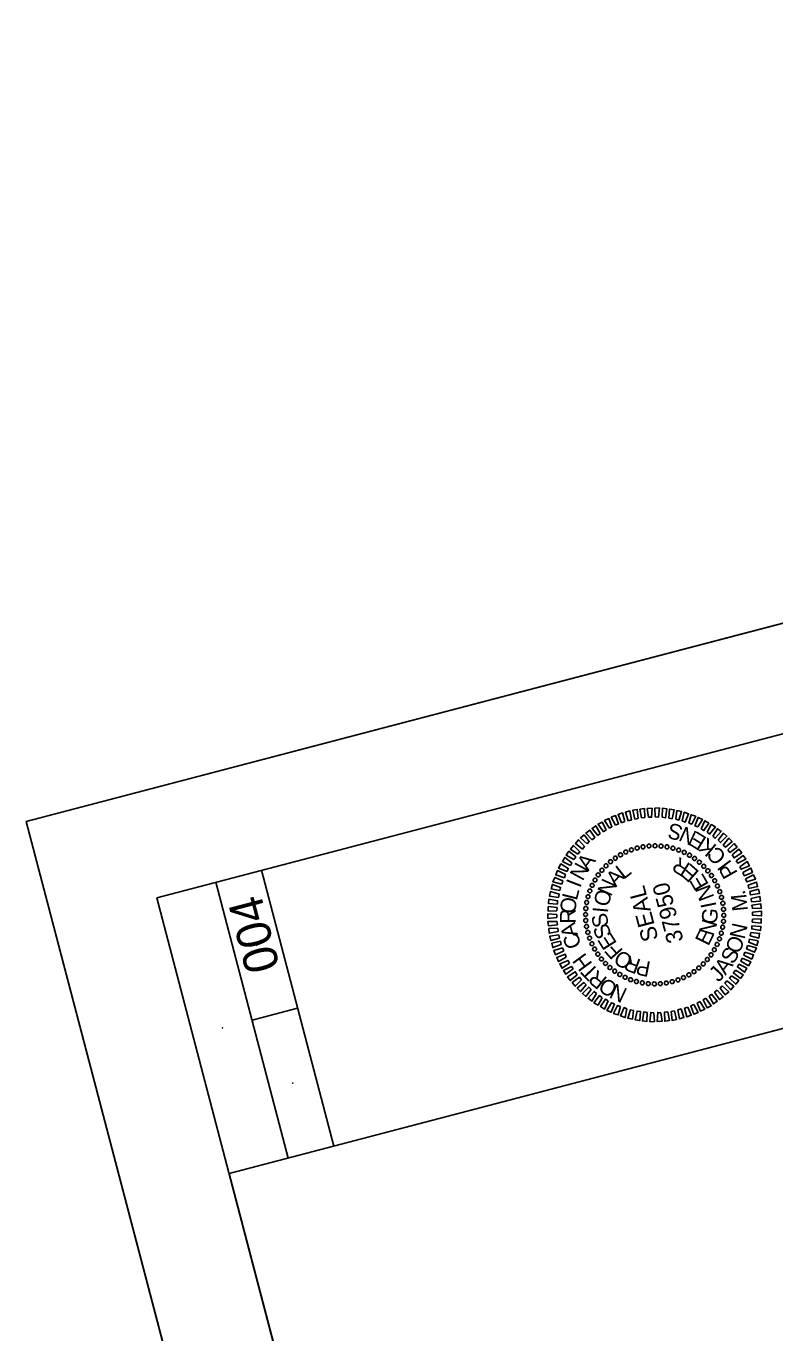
# Model space of a CAD drawing. Extents: x 1366711 to 1368206, y 878140 to 880064.
# Drawn here: x 1366710.8 to 1366973.2, y 879605.6 to 880063.8 of the extents above; entities that cross this region are included whole.
import ezdxf

# ---------------------------------------------------------------- set-up
doc = ezdxf.new("R2010")
doc.units = 0
for name, color, linetype in [('Exist Hydro Jurisdictional Stream or Body of Water Mitigable Cogo Number', 7, 'Continuous'), ('Exist Hydro Jurisdictional Stream or Body of Water NonMitigable', 7, 'Continuous'), ('Exist Hydro Jurisdictional Stream or Body of Water NonMitigable Text', 7, 'Continuous'), ('Sheet_Data_Field_CELL', 7, 'Continuous'), ('Sheet_Data_Text_CELL', 7, 'Continuous'), ('Sheet_Plan_CELL', 7, 'Continuous')]:
    doc.layers.add(name, color=color, linetype=linetype)

msp = doc.modelspace()

# ---------------------------------------------------------------- linework, layer by layer
at = {"layer": 'Exist Hydro Jurisdictional Stream or Body of Water Mitigable Cogo Number'}
for p, q in [((1367748.14, 880017.97), (1366756.62, 879758.15)), ((1367773.49, 879921.24), (1366781.97, 879661.42)), ((1366777.34, 879763.58), (1366802.69, 879666.85)), ((1366793.3, 879767.77), (1366818.65, 879671.03)), ((1366756.62, 879758.15), (1367168.57, 878186.24)), ((1366805.98, 879719.4), (1366790.02, 879715.22))]:
    msp.add_line(p, q, dxfattribs=at)
at = {"layer": 'Exist Hydro Jurisdictional Stream or Body of Water NonMitigable'}
for p in [(1367774.9, 880063.78), (1367141.8, 878140.46)]:
    msp.add_line(p, (1366710.84, 879784.92), dxfattribs=at)
for centre in [(1366791.66, 879741.49), (1366779.66, 879712.5), (1366804.33, 879693.13)]:
    msp.add_circle(centre, 0.06, dxfattribs=at)
at = {"layer": 'Sheet_Data_Field_CELL'}
for p, q in [((1366919.05, 879773.19), (1366919.05, 879773.19)), ((1366920.99, 879774.13), (1366920.99, 879774.13)), ((1366922.91, 879774.97), (1366922.91, 879774.97)), ((1366924.95, 879775.59), (1366924.95, 879775.59)), ((1366927.03, 879776.03), (1366927.03, 879776.03)), ((1366929.12, 879776.27), (1366929.12, 879776.27)), ((1366931.19, 879776.39), (1366931.19, 879776.39)), ((1366933.33, 879776.29), (1366933.33, 879776.29)), ((1366935.42, 879775.98), (1366935.42, 879775.98)), ((1366937.5, 879775.56), (1366937.5, 879775.56)), ((1366939.5, 879774.86), (1366939.5, 879774.86)), ((1366941.48, 879774.07), (1366941.48, 879774.07)), ((1366943.31, 879773.08), (1366943.31, 879773.08)), ((1366914.06, 879769.38), (1366914.06, 879769.38)), ((1366915.61, 879770.81), (1366915.61, 879770.81)), ((1366917.26, 879772.08), (1366917.26, 879772.08)), ((1366945.14, 879771.93), (1366945.14, 879771.93)), ((1366946.75, 879770.63), (1366946.75, 879770.63)), ((1366948.32, 879769.17), (1366948.32, 879769.17)), ((1366910.14, 879764.37), (1366910.14, 879764.37)), ((1366911.29, 879766.19), (1366911.29, 879766.19)), ((1366912.59, 879767.81), (1366912.59, 879767.81)), ((1366949.76, 879767.61), (1366949.76, 879767.61)), ((1366951.03, 879765.97), (1366951.03, 879765.97)), ((1366952.13, 879764.17), (1366952.13, 879764.17)), ((1366908.36, 879760.55), (1366908.36, 879760.55)), ((1366909.16, 879762.53), (1366909.16, 879762.53)), ((1366953.08, 879762.23), (1366953.08, 879762.23)), ((1366953.92, 879760.31), (1366953.92, 879760.31)), ((1366906.93, 879754.39), (1366906.93, 879754.39)), ((1366907.24, 879756.48), (1366907.24, 879756.48)), ((1366907.67, 879758.55), (1366907.67, 879758.55)), ((1366954.54, 879758.28), (1366954.54, 879758.28)), ((1366954.97, 879756.19), (1366954.97, 879756.19)), ((1366906.83, 879752.25), (1366906.83, 879752.25)), ((1366906.96, 879750.18), (1366906.96, 879750.18)), ((1366931.08, 879752.14), (1366931.08, 879752.14)), ((1366955.21, 879754.1), (1366955.21, 879754.1)), ((1366955.24, 879749.89), (1366955.24, 879749.89)), ((1366955.34, 879752.03), (1366955.34, 879752.03)), ((1366907.19, 879748.09), (1366907.19, 879748.09)), ((1366907.63, 879746), (1366907.63, 879746)), ((1366954.5, 879745.73), (1366954.5, 879745.73)), ((1366954.92, 879747.8), (1366954.92, 879747.8)), ((1366908.25, 879743.97), (1366908.25, 879743.97)), ((1366909.09, 879742.05), (1366909.09, 879742.05)), ((1366953.01, 879741.75), (1366953.01, 879741.75)), ((1366953.81, 879743.73), (1366953.81, 879743.73)), ((1366910.03, 879740.11), (1366910.03, 879740.11)), ((1366911.14, 879738.31), (1366911.14, 879738.31)), ((1366912.41, 879736.66), (1366912.41, 879736.66)), ((1366949.58, 879736.47), (1366949.58, 879736.47)), ((1366950.88, 879738.09), (1366950.88, 879738.09)), ((1366952.02, 879739.91), (1366952.02, 879739.91)), ((1366913.85, 879735.11), (1366913.85, 879735.11)), ((1366915.41, 879733.64), (1366915.41, 879733.64)), ((1366917.03, 879732.34), (1366917.03, 879732.34)), ((1366944.91, 879732.2), (1366944.91, 879732.2)), ((1366946.56, 879733.46), (1366946.56, 879733.46)), ((1366948.11, 879734.9), (1366948.11, 879734.9)), ((1366918.86, 879731.2), (1366918.86, 879731.2)), ((1366920.69, 879730.21), (1366920.69, 879730.21)), ((1366922.67, 879729.41), (1366922.67, 879729.41)), ((1366924.67, 879728.72), (1366924.67, 879728.72)), ((1366926.74, 879728.3), (1366926.74, 879728.3)), ((1366928.84, 879727.99), (1366928.84, 879727.99)), ((1366930.97, 879727.88), (1366930.97, 879727.88)), ((1366933.04, 879728.01), (1366933.04, 879728.01)), ((1366935.13, 879728.25), (1366935.13, 879728.25)), ((1366937.22, 879728.69), (1366937.22, 879728.69)), ((1366939.25, 879729.31), (1366939.25, 879729.31)), ((1366941.17, 879730.14), (1366941.17, 879730.14)), ((1366943.11, 879731.09), (1366943.11, 879731.09))]:
    msp.add_line(p, q, dxfattribs=at)
for points in [[(1366917.35, 879783.54), (1366915.85, 879786.38), (1366917.39, 879786.97), (1366918.41, 879784.04)], [(1366919.5, 879784.45), (1366918.28, 879787.37), (1366919.84, 879787.9), (1366920.59, 879784.86)], [(1366921.81, 879785.14), (1366920.83, 879788.13), (1366922.41, 879788.57), (1366922.93, 879785.46)], [(1366924.15, 879785.75), (1366923.4, 879788.8), (1366924.96, 879789.14), (1366925.29, 879785.97)], [(1366926.45, 879786.15), (1366925.89, 879789.2), (1366927.52, 879789.46), (1366927.63, 879786.23)], [(1366928.93, 879786.44), (1366928.49, 879789.43), (1366930.16, 879789.55), (1366930.01, 879786.34)], [(1366931.32, 879786.46), (1366931.12, 879789.51), (1366932.74, 879789.62), (1366932.4, 879786.37)], [(1366933.75, 879786.39), (1366933.78, 879789.51), (1366935.39, 879789.31), (1366934.87, 879786.15)], [(1366936.06, 879786.04), (1366936.32, 879789.22), (1366937.95, 879788.93), (1366937.21, 879785.86)], [(1366938.46, 879785.71), (1366938.88, 879788.68), (1366940.52, 879788.39), (1366939.5, 879785.4)], [(1366940.77, 879785.15), (1366941.43, 879788.15), (1366943, 879787.58), (1366941.82, 879784.65)], [(1366943.02, 879784.28), (1366943.9, 879787.23), (1366945.49, 879786.73), (1366944.08, 879783.92)], [(1366909.19, 879778.49), (1366907.02, 879780.84), (1366908.34, 879781.87), (1366910.08, 879779.24)], [(1366911.14, 879779.94), (1366909.13, 879782.44), (1366910.43, 879783.36), (1366911.98, 879780.68)], [(1366913.16, 879781.31), (1366911.25, 879783.99), (1366912.71, 879784.7), (1366914.05, 879781.91)], [(1366915.23, 879782.5), (1366913.53, 879785.18), (1366915.03, 879785.9), (1366916.13, 879783.05)], [(1366945.18, 879783.38), (1366946.31, 879786.31), (1366947.81, 879785.63), (1366946.2, 879782.97)], [(1366947.4, 879782.25), (1366948.65, 879785.16), (1366950.04, 879784.29), (1366948.36, 879781.72)], [(1366949.46, 879781.18), (1366950.93, 879783.79), (1366952.36, 879782.99), (1366950.36, 879780.47)], [(1366951.43, 879779.72), (1366953.1, 879782.34), (1366954.42, 879781.36), (1366952.28, 879779.01)], [(1366905.74, 879775.22), (1366903.29, 879777.19), (1366904.43, 879778.46), (1366906.49, 879776.13)], [(1366907.45, 879777), (1366905.09, 879779.15), (1366906.36, 879780.16), (1366908.18, 879777.81)], [(1366953.32, 879778.34), (1366955.2, 879780.73), (1366956.43, 879779.77), (1366954.16, 879777.48)], [(1366955.05, 879776.62), (1366957.08, 879779.05), (1366958.23, 879777.82), (1366955.86, 879775.9)], [(1366902.76, 879771.57), (1366900.06, 879773.12), (1366901.04, 879774.45), (1366903.5, 879772.48)], [(1366904.18, 879773.47), (1366901.59, 879775.2), (1366902.69, 879776.47), (1366904.9, 879774.28)], [(1366956.73, 879774.94), (1366958.92, 879777.16), (1366959.97, 879775.9), (1366957.44, 879774.03)], [(1366958.28, 879773.17), (1366960.64, 879775.14), (1366961.59, 879773.9), (1366958.89, 879772.08)], [(1366959.66, 879771.1), (1366962.15, 879772.95), (1366962.98, 879771.63), (1366960.26, 879770.21)], [(1366900.38, 879767.34), (1366897.43, 879768.57), (1366898.23, 879770), (1366900.83, 879768.42)], [(1366901.54, 879769.47), (1366898.79, 879770.86), (1366899.6, 879772.29), (1366902.09, 879770.38)], [(1366960.89, 879769.04), (1366963.55, 879770.84), (1366964.32, 879769.34), (1366961.4, 879768.13)], [(1366962.03, 879766.95), (1366964.8, 879768.53), (1366965.37, 879767.03), (1366962.49, 879765.87)], [(1366898.58, 879762.87), (1366895.42, 879763.74), (1366896.06, 879765.23), (1366898.85, 879764.05)], [(1366899.44, 879765.17), (1366896.4, 879766.17), (1366897.08, 879767.67), (1366899.84, 879766.24)], [(1366962.94, 879764.79), (1366965.77, 879766.14), (1366966.4, 879764.62), (1366963.39, 879763.72)], [(1366963.82, 879762.54), (1366966.78, 879763.62), (1366967.16, 879762.07), (1366964.09, 879761.41)], [(1366897.36, 879758.27), (1366894.29, 879758.66), (1366894.54, 879760.28), (1366897.59, 879759.44)], [(1366897.83, 879760.71), (1366894.83, 879761.22), (1366895.23, 879762.83), (1366898.14, 879761.75)], [(1366964.41, 879760.29), (1366967.43, 879761.14), (1366967.81, 879759.59), (1366964.67, 879759.16)], [(1366896.82, 879753.6), (1366893.74, 879753.49), (1366893.8, 879755.06), (1366896.87, 879754.67)], [(1366897.07, 879755.93), (1366893.84, 879756.18), (1366894.03, 879757.64), (1366897.09, 879757.09)], [(1366964.92, 879757.93), (1366967.99, 879758.59), (1366968.14, 879756.98), (1366965.04, 879756.76)], [(1366965.17, 879755.59), (1366968.26, 879756.01), (1366968.46, 879754.41), (1366965.35, 879754.44)], [(1366896.84, 879751.2), (1366893.69, 879750.82), (1366893.62, 879752.5), (1366896.8, 879752.24)], [(1366896.99, 879748.69), (1366893.9, 879748.27), (1366893.7, 879749.87), (1366896.82, 879749.84)], [(1366965.35, 879750.68), (1366968.43, 879750.79), (1366968.37, 879749.22), (1366965.3, 879749.61)], [(1366965.33, 879753.08), (1366968.48, 879753.46), (1366968.55, 879751.78), (1366965.37, 879752.04)], [(1366897.25, 879746.35), (1366894.17, 879745.69), (1366894.02, 879747.3), (1366897.12, 879747.52)], [(1366964.8, 879746.01), (1366967.87, 879745.62), (1366967.63, 879743.99), (1366964.58, 879744.84)], [(1366965.1, 879748.35), (1366968.33, 879748.1), (1366968.14, 879746.65), (1366965.08, 879747.19)], [(1366897.76, 879743.99), (1366894.74, 879743.14), (1366894.36, 879744.68), (1366897.5, 879745.12)], [(1366898.34, 879741.74), (1366895.39, 879740.66), (1366895, 879742.21), (1366898.08, 879742.87)], [(1366963.59, 879741.41), (1366966.74, 879740.53), (1366966.1, 879739.05), (1366963.32, 879740.23)], [(1366964.33, 879743.57), (1366967.34, 879743.06), (1366966.94, 879741.45), (1366964.03, 879742.53)], [(1366899.23, 879739.48), (1366896.39, 879738.13), (1366895.77, 879739.66), (1366898.77, 879740.56)], [(1366900.13, 879737.33), (1366897.37, 879735.75), (1366896.8, 879737.24), (1366899.68, 879738.41)], [(1366901.27, 879735.24), (1366898.62, 879733.44), (1366897.85, 879734.93), (1366900.76, 879736.15)], [(1366961.79, 879736.93), (1366964.74, 879735.71), (1366963.93, 879734.28), (1366961.33, 879735.86)], [(1366962.73, 879739.11), (1366965.77, 879738.11), (1366965.09, 879736.61), (1366962.33, 879738.04)], [(1366902.5, 879733.18), (1366900.01, 879731.33), (1366899.19, 879732.65), (1366901.9, 879734.06)], [(1366903.89, 879731.11), (1366901.53, 879729.14), (1366900.58, 879730.38), (1366903.28, 879732.19)], [(1366959.41, 879732.71), (1366962.1, 879731.16), (1366961.12, 879729.83), (1366958.66, 879731.8)], [(1366960.63, 879734.8), (1366963.37, 879733.42), (1366962.57, 879731.99), (1366960.08, 879733.9)], [(1366905.44, 879729.34), (1366903.25, 879727.12), (1366902.2, 879728.38), (1366904.73, 879730.24)], [(1366907.11, 879727.65), (1366905.09, 879725.23), (1366903.94, 879726.46), (1366906.31, 879728.38)], [(1366954.72, 879727.28), (1366957.07, 879725.13), (1366955.8, 879724.13), (1366953.99, 879726.47)], [(1366956.42, 879729.06), (1366958.88, 879727.09), (1366957.74, 879725.82), (1366955.68, 879728.15)], [(1366957.99, 879730.81), (1366960.58, 879729.07), (1366959.48, 879727.81), (1366957.26, 879730)], [(1366908.85, 879725.93), (1366906.96, 879723.55), (1366905.74, 879724.51), (1366908.01, 879726.8)], [(1366910.74, 879724.56), (1366909.07, 879721.93), (1366907.74, 879722.92), (1366909.89, 879725.27)], [(1366912.7, 879723.1), (1366911.23, 879720.48), (1366909.8, 879721.29), (1366911.81, 879723.81)], [(1366914.76, 879722.03), (1366913.52, 879719.12), (1366912.13, 879719.98), (1366913.81, 879722.56)], [(1366949.01, 879722.97), (1366950.91, 879720.29), (1366949.45, 879719.58), (1366948.12, 879722.37)], [(1366951.03, 879724.34), (1366953.03, 879721.84), (1366951.74, 879720.93), (1366950.18, 879723.6)], [(1366952.98, 879725.79), (1366955.14, 879723.44), (1366953.82, 879722.41), (1366952.09, 879725.03)], [(1366916.98, 879720.9), (1366915.85, 879717.97), (1366914.36, 879718.65), (1366915.97, 879721.31)], [(1366919.14, 879720), (1366918.27, 879717.04), (1366916.67, 879717.55), (1366918.09, 879720.36)], [(1366921.39, 879719.13), (1366920.73, 879716.13), (1366919.17, 879716.69), (1366920.35, 879719.63)], [(1366923.71, 879718.57), (1366923.29, 879715.59), (1366921.65, 879715.89), (1366922.67, 879718.88)], [(1366926.11, 879718.24), (1366925.85, 879715.06), (1366924.21, 879715.35), (1366924.95, 879718.42)], [(1366928.41, 879717.89), (1366928.39, 879714.77), (1366926.77, 879714.97), (1366927.29, 879718.12)], [(1366930.84, 879717.81), (1366931.05, 879714.76), (1366929.42, 879714.66), (1366929.76, 879717.91)], [(1366933.24, 879717.84), (1366933.68, 879714.85), (1366932.01, 879714.73), (1366932.16, 879717.94)], [(1366935.72, 879718.13), (1366936.27, 879715.08), (1366934.64, 879714.82), (1366934.54, 879718.05)], [(1366938.01, 879718.53), (1366938.77, 879715.48), (1366937.21, 879715.14), (1366936.87, 879718.3)], [(1366940.35, 879719.13), (1366941.34, 879716.15), (1366939.76, 879715.71), (1366939.24, 879718.82)], [(1366942.66, 879719.83), (1366943.88, 879716.91), (1366942.33, 879716.38), (1366941.57, 879719.42)], [(1366944.82, 879720.74), (1366946.31, 879717.9), (1366944.78, 879717.31), (1366943.75, 879720.24)], [(1366946.93, 879721.78), (1366948.64, 879719.1), (1366947.13, 879718.38), (1366946.03, 879721.23)]]:
    msp.add_lwpolyline(points, close=True, dxfattribs=at)
for centre, major_axis, ratio in [((1366917.3, 879772.05), (-0.394, 0.573), 0.999706), ((1366919.09, 879773.18), (-0.343, 0.605), 0.999706), ((1366920.97, 879774.14), (-0.289, 0.632), 0.999706), ((1366922.92, 879774.94), (-0.234, 0.655), 0.999706), ((1366924.94, 879775.57), (-0.176, 0.673), 0.999706), ((1366927.01, 879776.01), (-0.117, 0.685), 0.999706), ((1366929.1, 879776.28), (-0.058, 0.693), 0.999706), ((1366931.22, 879776.36), (0.002, 0.695), 0.999706), ((1366933.33, 879776.25), (0.063, 0.693), 0.999706), ((1366935.42, 879775.97), (0.122, 0.684), 0.999707), ((1366937.48, 879775.5), (0.181, 0.671), 0.999707), ((1366939.49, 879774.85), (0.239, 0.653), 0.999707), ((1366941.44, 879774.03), (0.295, 0.63), 0.999708), ((1366943.31, 879773.05), (0.348, 0.602), 0.999708), ((1366945.08, 879771.9), (0.4, 0.569), 0.999709), ((1366912.61, 879767.81), (-0.528, 0.452), 0.999707), ((1366914.05, 879769.36), (-0.487, 0.496), 0.999707), ((1366915.62, 879770.78), (-0.442, 0.537), 0.999707), ((1366946.75, 879770.61), (0.448, 0.532), 0.999709), ((1366948.3, 879769.17), (0.493, 0.491), 0.99971), ((1366949.72, 879767.6), (0.534, 0.446), 0.99971), ((1366910.17, 879764.36), (-0.599, 0.353), 0.999708), ((1366911.32, 879766.14), (-0.566, 0.404), 0.999708), ((1366951, 879765.92), (0.571, 0.397), 0.99971), ((1366952.13, 879764.13), (0.603, 0.346), 0.99971), ((1366907.72, 879758.53), (-0.67, 0.186), 0.99971), ((1366908.37, 879760.55), (-0.651, 0.244), 0.999709), ((1366909.19, 879762.49), (-0.627, 0.3), 0.999709), ((1366953.09, 879762.25), (0.631, 0.291), 0.999711), ((1366953.89, 879760.3), (0.655, 0.235), 0.999711), ((1366954.51, 879758.28), (0.673, 0.176), 0.999711), ((1366906.97, 879754.38), (-0.692, 0.066), 0.99971), ((1366907.25, 879756.47), (-0.684, 0.127), 0.99971), ((1366954.96, 879756.21), (0.686, 0.116), 0.999711), ((1366955.22, 879754.11), (0.693, 0.056), 0.999711), ((1366906.86, 879752.27), (-0.695, 0.005), 0.99971), ((1366906.94, 879750.16), (-0.693, -0.056), 0.999711), ((1366955.2, 879749.89), (0.692, -0.066), 0.99971), ((1366955.3, 879752), (0.695, -0.005), 0.99971), ((1366907.21, 879748.06), (-0.686, -0.116), 0.999711), ((1366907.65, 879746), (-0.673, -0.176), 0.999711), ((1366954.44, 879745.74), (0.67, -0.186), 0.99971), ((1366954.91, 879747.8), (0.684, -0.127), 0.99971), ((1366908.28, 879743.98), (-0.655, -0.235), 0.999711), ((1366909.08, 879742.02), (-0.631, -0.291), 0.999711), ((1366910.04, 879740.14), (-0.603, -0.346), 0.99971), ((1366951.99, 879739.91), (0.599, -0.353), 0.999708), ((1366952.98, 879741.78), (0.627, -0.3), 0.999709), ((1366953.8, 879743.73), (0.651, -0.244), 0.999709), ((1366911.17, 879738.35), (-0.571, -0.397), 0.99971), ((1366912.44, 879736.67), (-0.534, -0.446), 0.99971), ((1366949.55, 879736.47), (0.528, -0.452), 0.999707), ((1366950.85, 879738.14), (0.566, -0.404), 0.999708), ((1366913.86, 879735.1), (-0.493, -0.491), 0.99971), ((1366915.41, 879733.67), (-0.448, -0.532), 0.999709), ((1366917.08, 879732.37), (-0.4, -0.569), 0.999709), ((1366918.86, 879731.23), (-0.348, -0.602), 0.999708), ((1366943.08, 879731.09), (0.343, -0.605), 0.999706), ((1366944.87, 879732.22), (0.394, -0.573), 0.999706), ((1366946.55, 879733.5), (0.442, -0.537), 0.999707), ((1366948.12, 879734.92), (0.487, -0.496), 0.999707), ((1366920.73, 879730.24), (-0.295, -0.63), 0.999708), ((1366922.67, 879729.42), (-0.239, -0.653), 0.999707), ((1366924.69, 879728.78), (-0.181, -0.671), 0.999707), ((1366926.75, 879728.31), (-0.122, -0.684), 0.999707), ((1366928.84, 879728.02), (-0.063, -0.693), 0.999706), ((1366930.95, 879727.92), (-0.002, -0.695), 0.999706), ((1366933.06, 879728), (0.058, -0.693), 0.999706), ((1366935.16, 879728.26), (0.117, -0.685), 0.999706), ((1366937.22, 879728.71), (0.176, -0.673), 0.999706), ((1366939.24, 879729.33), (0.234, -0.655), 0.999706), ((1366941.2, 879730.13), (0.289, -0.632), 0.999706)]:
    msp.add_ellipse(centre, major_axis=major_axis, ratio=ratio, dxfattribs=at)
at = {"layer": 'Sheet_Data_Text_CELL'}
msp.add_lwpolyline([(1367141.8, 878140.46), (1366710.84, 879784.92), (1367774.9, 880063.78), (1368205.86, 878419.32)], close=True, dxfattribs=at)
at = {"layer": 'Sheet_Plan_CELL'}
msp.add_lwpolyline([(1367168.57, 878186.24), (1366781.97, 879661.42), (1367773.49, 879921.26), (1368160.08, 878446.08)], close=True, dxfattribs=at)

# ---------------------------------------------------------------- texts
at = {"layer": 'Exist Hydro Jurisdictional Stream or Body of Water NonMitigable Text'}
msp.add_text('004', height=12.003, rotation=104.6851, dxfattribs=at).set_placement((1366799.84, 879733.69))
at = {"layer": 'Sheet_Data_Field_CELL'}
for s, height, rotation, p in [('S', 5.46, 164.7452, (1366941.34, 879783.23)), ('N', 5.46, 155.468, (1366946.21, 879781.17)), ('E', 5.46, 148.3514, (1366949.69, 879779.07)), ('K', 5.46, 140.5331, (1366953.18, 879776.29)), ('A', 5.45, 54.3023, (1366907.83, 879767.27)), ('C', 5.46, 131.9391, (1366956.54, 879772.71)), ('N', 5.45, 61.5041, (1366905.85, 879763.76)), ('L', 5.45, 38.086, (1366920.18, 879764.37)), ('R', 5.45, 148.1665, (1366943.91, 879769.88)), ('E', 5.45, 138.8091, (1366947.02, 879767.19)), ('I', 5.46, 126.7985, (1366958.28, 879770.35)), ('P', 5.46, 119.6819, (1366960.33, 879766.84)), ('I', 5.45, 68.7053, (1366904.97, 879761.35)), ('N', 5.45, 66.1618, (1366915.8, 879758.32)), ('A', 5.45, 47.4454, (1366917.48, 879761.65)), ('E', 5.45, 120.0968, (1366950.22, 879762.77)), ('L', 5.45, 75.906, (1366903.8, 879756.96)), ('O', 5.45, 75.5187, (1366914.82, 879754.69)), ('SEAL', 5.793, 104.8532, (1366932.46, 879743.65)), ('37950', 5.794, 104.6851, (1366941.25, 879743.14)), ('N', 5.44, 110.7415, (1366952.07, 879758.32)), ('M', 5.46, 95.6821, (1366963.78, 879753.67)), ('.', 5.46, 105.4395, (1366963.05, 879759.19)), ('O', 5.44, 83.1063, (1366903.23, 879752.38)), ('I', 5.45, 84.8748, (1366914.69, 879752.64)), ('I', 5.44, 101.3863, (1366952.8, 879755.17)), ('R', 5.45, 90.3062, (1366903.41, 879749.07)), ('A', 5.44, 104.7054, (1366904.32, 879745.12)), ('S', 5.44, 103.5855, (1366915.16, 879748.46)), ('N', 5.45, 73.3191, (1366951.65, 879744.47)), ('G', 5.45, 82.6754, (1366952.75, 879748.59)), ('C', 5.44, 111.905, (1366905.62, 879741.52)), ('S', 5.44, 112.9407, (1366916.15, 879745.13)), ('E', 5.45, 122.2961, (1366918.03, 879742.19)), ('E', 5.45, 63.9621, (1366949.92, 879740.97)), ('N', 5.46, 77.4417, (1366962.61, 879743.36)), ('F', 5.44, 131.6521, (1366920.26, 879739.61)), ('S', 5.46, 60.42, (1366958.66, 879734.51)), ('O', 5.46, 67.6659, (1366960.67, 879738.13)), ('H', 5.45, 126.3045, (1366909.47, 879734.98)), ('O', 5.45, 150.3663, (1366923.86, 879737.31)), ('R', 5.45, 159.7247, (1366926.6, 879736.33)), ('A', 5.46, 52.2692, (1366955.88, 879730.78)), ('T', 5.45, 133.5048, (1366911.85, 879732.39)), ('R', 5.45, 140.7056, (1366914.79, 879729.8)), ('P', 5.45, 169.0839, (1366929.99, 879735.67)), ('J', 5.46, 46.2588, (1366953.51, 879728.3)), ('O', 5.45, 147.9068, (1366918.57, 879727.4)), ('N', 5.45, 155.1085, (1366921.87, 879726.02))]:
    msp.add_text(s, height=height, rotation=rotation, dxfattribs=at).set_placement(p)

doc.saveas('drawing.dxf')
